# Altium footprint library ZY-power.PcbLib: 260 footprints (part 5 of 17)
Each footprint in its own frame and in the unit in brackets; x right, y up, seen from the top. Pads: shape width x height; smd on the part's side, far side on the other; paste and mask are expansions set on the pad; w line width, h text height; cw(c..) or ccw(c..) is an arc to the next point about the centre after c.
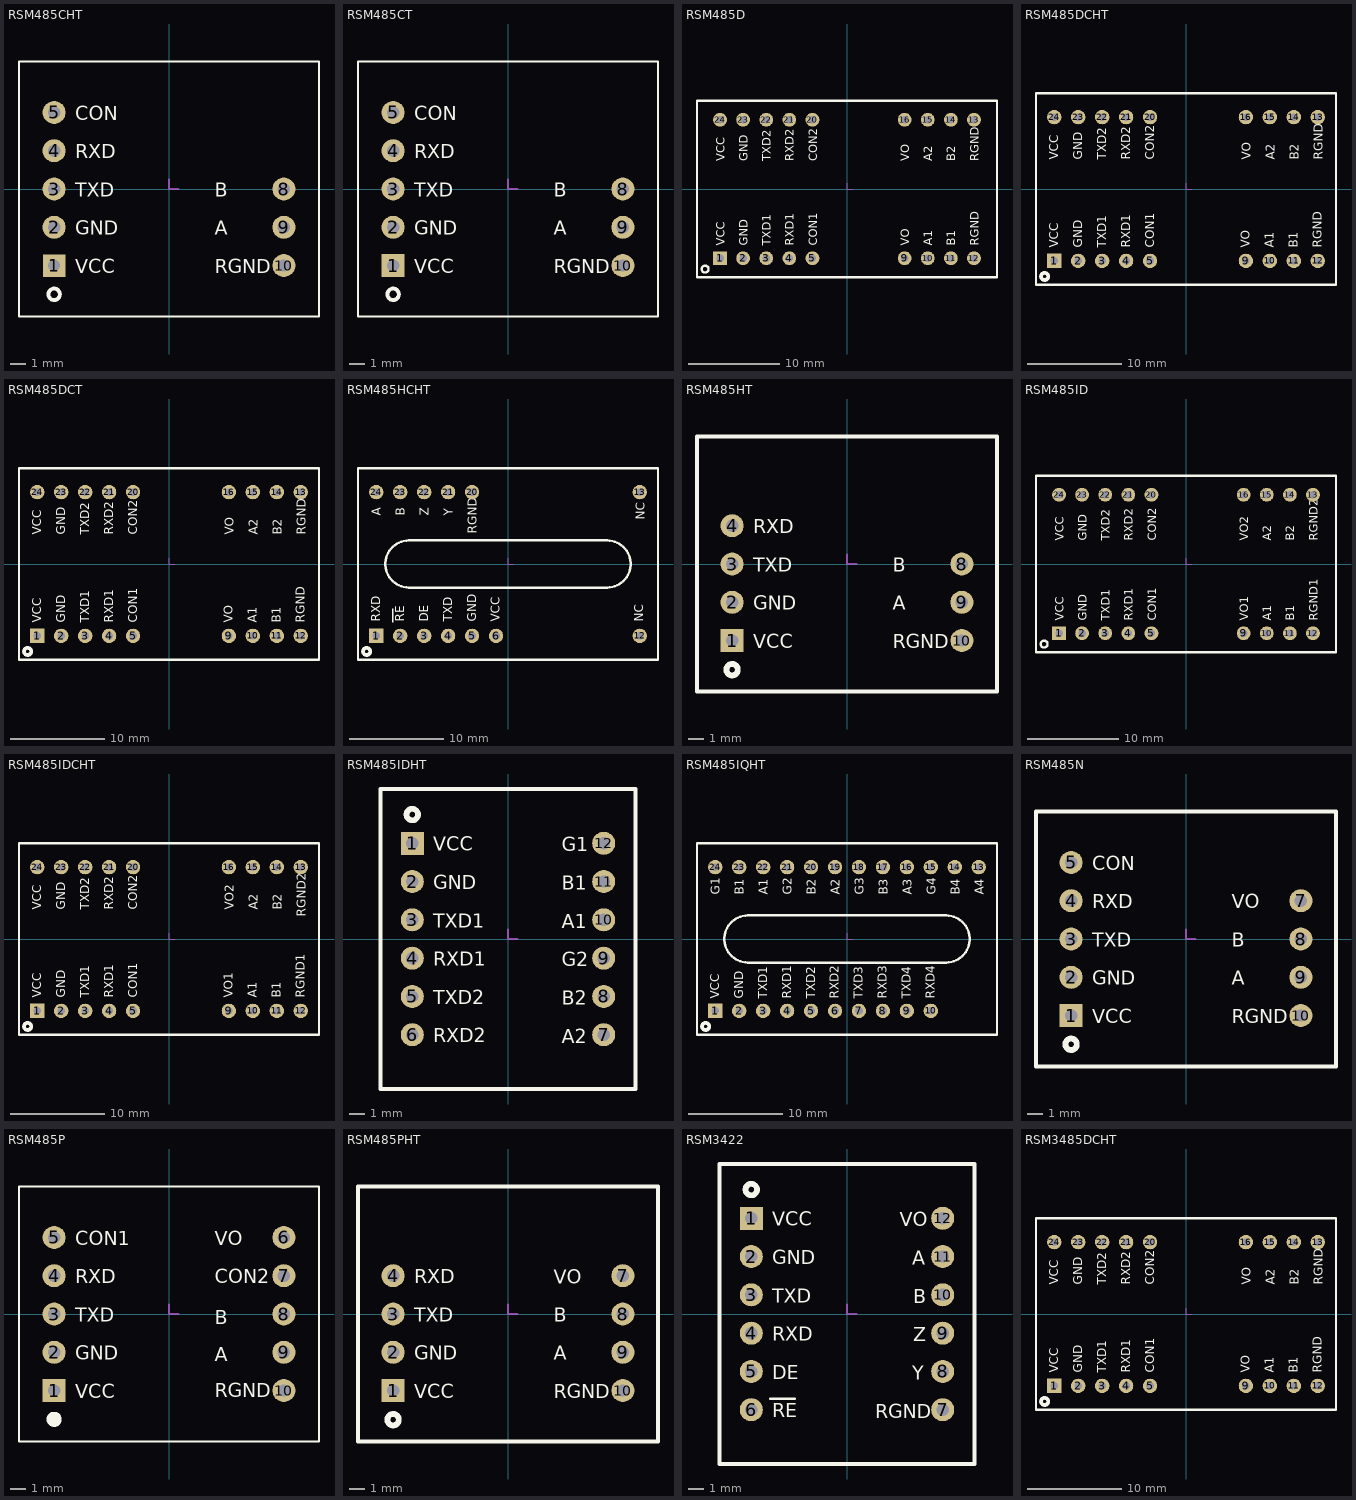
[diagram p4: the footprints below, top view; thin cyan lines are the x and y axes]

## RSM485CHT [mil] "嵌入式隔离RS-485收发器"
height 275.59
pads (8):
  rect 59.06x59.06 hole 31.5: 1(-300,-200)
  round 60 hole 32: 2(-300,-100) 3(-300,0) 4(-300,100) 5(-300,200) 8(300,0) 9(300,-100) 10(300,-200)
Top Overlay:
  circle w10: c-300,-275 r15
  lines w5: -391.73,-332.68 391.73,-332.68 391.73,332.68 -391.73,332.68 -391.73,-332.68
  text "A" at 120,-120 h36
  text "B" at 120,-20 h36
  text "RGND" at 120,-220 h36
  text "TXD" at -245,-20 h36
  text "RXD" at -245,80 h36
  text "GND" at -245,-120 h36
  text "CON" at -245,180 h36
  text "VCC" at -245,-220 h36
Mechanical 15:
  lines w5: 0,25 0,0 25,0

## RSM485CT [mil] "嵌入式隔离RS-485收发器"
height 275.59
pads (8):
  rect 60x60 hole 32: 1(-300,-200)
  round 60 hole 32: 2(-300,-100) 3(-300,0) 4(-300,100) 5(-300,200) 8(300,0) 9(300,-100) 10(300,-200)
Top Overlay:
  circle w10: c-300,-275 r15
  lines w5: -391.73,-332.68 -391.73,332.68 391.73,332.68 391.73,-332.68 -391.73,-332.68
  text "VCC" at -245,-220 h36
  text "CON" at -245,180 h36
  text "GND" at -245,-120 h36
  text "RXD" at -245,80 h36
  text "TXD" at -245,-20 h36
  text "RGND" at 120,-220 h36
  text "B" at 120,-20 h36
  text "A" at 120,-120 h36
Mechanical 15:
  lines w5: 0,25 0,0 25,0

## RSM485D [mil]
height 360
pads (18):
  rect 60x60 hole 32: 1(-550,-300)
  round 60 hole 32: 2(-450,-300) 3(-350,-300) 4(-250,-300) 5(-150,-300) 9(250,-300) 10(350,-300) 11(450,-300) 12(550,-300) 13(550,300) 14(450,300) 15(350,300) 16(250,300) 20(-150,300) 21(-250,300) 22(-350,300) 23(-450,300) 24(-550,300)
Top Overlay:
  circle w10: c-615,-347 r15
  lines w10: -650,-382 -650,382 650,382 650,-382 -650,-382
  text "VO" at 270,120 h36
  text "VO" at 270,-245 h36
  text "RGND" at 570,-245 h36
  text "A1" at 370,-245 h36
  text "B1" at 470,-245 h36
  text "RGND" at 570,120 h36
  text "A2" at 370,120 h36
  text "B2" at 470,120 h36
  text "TXD2" at -330,120 h36
  text "RXD2" at -230,120 h36
  text "GND" at -430,120 h36
  text "CON2" at -130,120 h36
  text "VCC" at -530,120 h36
  text "VCC" at -530,-245 h36
  text "CON1" at -130,-245 h36
  text "GND" at -430,-245 h36
  text "RXD1" at -230,-245 h36
  text "TXD1" at -330,-245 h36
Mechanical 15:
  lines w5: 0,25 0,0 25,0

## RSM485DCHT [mil]
height 255.91
pads (18):
  rect 60x60 hole 32: 1(-550,-300)
  round 60 hole 32: 2(-450,-300) 3(-350,-300) 4(-250,-300) 5(-150,-300) 9(250,-300) 10(350,-300) 11(450,-300) 12(550,-300) 13(550,300) 14(450,300) 15(350,300) 16(250,300) 20(-150,300) 21(-250,300) 22(-350,300) 23(-450,300) 24(-550,300)
Top Overlay:
  circle w15: c-590,-365 r15
  lines w10: -625.98,-399.61 625.98,-399.61 625.98,399.61 -625.98,399.61 -625.98,-399.61
  text "VCC" at -533,-245 h36
  text "GND" at -433,-245 h36
  text "TXD1" at -333,-245 h36
  text "RXD1" at -233,-245 h36
  text "CON1" at -133,-245 h36
  text "VO" at 267,-245 h36
  text "A1" at 367,-245 h36
  text "B1" at 467,-245 h36
  text "RGND" at 567,-245 h36
  text "RGND" at 570,123 h36
  text "B2" at 469.73,123 h36
  text "A2" at 369.45,123 h36
  text "VO" at 269.18,123 h36
  text "VCC" at -533,123 h36
  text "GND" at -432.73,123 h36
  text "TXD2" at -332.45,123 h36
  text "CON2" at -131.91,123 h36
  text "RXD2" at -232.18,123 h36
Mechanical 15:
  lines w5: 0,25 0,0 25,0

## RSM485DCT [mil]
height 374.02
pads (18):
  rect 60x60 hole 32: 1(-550,-300)
  round 60 hole 32: 2(-450,-300) 3(-350,-300) 4(-250,-300) 5(-150,-300) 9(250,-300) 10(350,-300) 11(450,-300) 12(550,-300) 13(550,300) 14(450,300) 15(350,300) 16(250,300) 20(-150,300) 21(-250,300) 22(-350,300) 23(-450,300) 24(-550,300)
Top Overlay:
  circle w15: c-590,-365 r15
  lines w10: -625.98,-399.61 -625.98,399.61 625.98,399.61 625.98,-399.61 -625.98,-399.61
  text "RXD2" at -232.18,123 h36
  text "CON2" at -131.91,123 h36
  text "TXD2" at -332.45,123 h36
  text "GND" at -432.73,123 h36
  text "VCC" at -533,123 h36
  text "VO" at 269.18,123 h36
  text "A2" at 369.45,123 h36
  text "B2" at 469.73,123 h36
  text "RGND" at 570,123 h36
  text "RGND" at 567,-245 h36
  text "B1" at 467,-245 h36
  text "A1" at 367,-245 h36
  text "VO" at 267,-245 h36
  text "CON1" at -133,-245 h36
  text "RXD1" at -233,-245 h36
  text "TXD1" at -333,-245 h36
  text "GND" at -433,-245 h36
  text "VCC" at -533,-245 h36
Mechanical 15:
  lines w5: 0,25 0,0 25,0

## RSM485HCHT [mil]
height 255.91
pads (13):
  rect 60x60 hole 32: 1(-550,-300)
  round 60 hole 32: 2(-450,-300) 3(-350,-300) 4(-250,-300) 5(-150,-300) 6(-50,-300) 12(550,-300) 13(550,300) 20(-150,300) 21(-250,300) 22(-350,300) 23(-450,300) 24(-550,300)
Top Overlay:
  circle w15: c-590,-365 r15
  lines w6: -481.1,-243 -481.1,-186.67
  lines w10: -625.98,-399.61 -625.98,399.61 625.98,399.61 625.98,-399.61 -625.98,-399.61 ; -413.39,-98.43 cw(c-413.39,0) -413.39,98.43 413.39,98.43 cw(c413.39,0) 413.39,-98.43 -413.39,-98.43
  text "VCC" at -33.56,-242 h36
  text "Y" at -231.45,201 h36
  text "RGND" at -131.27,126.94 h36
  text "Z" at -331.64,201 h36
  text "B" at -431.82,201 h36
  text "A" at -532,201 h36
  text "NC" at 570,185 h36
  text "GND" at -133.44,-242 h36
  text "TXD" at -233.33,-242 h36
  text "DE" at -333.22,-242 h36
  text "RE" at -433.11,-242 h36
  text "RXD" at -533,-242 h36
  text "NC" at 565,-242 h36
Mechanical 15:
  lines w5: 0,25 0,0 25,0

## RSM485HT [mil]
height 277.56
pads (7):
  rect 60x60 hole 32: 1(-300,-200)
  round 60 hole 32: 2(-300,-100) 3(-300,0) 4(-300,100) 8(300,0) 9(300,-100) 10(300,-200)
Top Overlay:
  circle w15: c-300,-276 r15
  lines w10: -391.73,-332.68 -391.73,332.68 391.73,332.68 391.73,-332.68 -391.73,-332.68
  text "VCC" at -245,-220 h36
  text "GND" at -245,-120 h36
  text "RXD" at -245,80 h36
  text "TXD" at -245,-20 h36
  text "RGND" at 120,-220 h36
  text "B" at 120,-20 h36
  text "A" at 120,-120 h36
Mechanical 15:
  lines w5: 0,25 0,0 25,0

## RSM485ID [mil]
height 360
pads (18):
  rect 60x60 hole 32: 1(-550,-300)
  round 60 hole 32: 2(-450,-300) 3(-350,-300) 4(-250,-300) 5(-150,-300) 9(250,-300) 10(350,-300) 11(450,-300) 12(550,-300) 13(550,300) 14(450,300) 15(350,300) 16(250,300) 20(-150,300) 21(-250,300) 22(-350,300) 23(-450,300) 24(-550,300)
Top Overlay:
  circle w10: c-615,-347 r15
  lines w10: -650,-382 -650,382 650,382 650,-382 -650,-382
  text "VO2" at 270,100 h36
  text "VO1" at 270,-245 h36
  text "RGND1" at 570,-245 h36
  text "A1" at 370,-245 h36
  text "B1" at 470,-245 h36
  text "RGND2" at 570,100 h36
  text "A2" at 370,100 h36
  text "B2" at 470,100 h36
  text "TXD2" at -330,100 h36
  text "RXD2" at -230,100 h36
  text "GND" at -430,100 h36
  text "CON2" at -130,100 h36
  text "VCC" at -530,100 h36
  text "VCC" at -530,-245 h36
  text "CON1" at -130,-245 h36
  text "GND" at -430,-245 h36
  text "RXD1" at -230,-245 h36
  text "TXD1" at -330,-245 h36
Mechanical 15:
  lines w5: 0,25 0,0 25,0

## RSM485IDCHT [mil]
height 255.91
pads (18):
  rect 60x60 hole 32: 1(-550,-300)
  round 60 hole 32: 2(-450,-300) 3(-350,-300) 4(-250,-300) 5(-150,-300) 9(250,-300) 10(350,-300) 11(450,-300) 12(550,-300) 13(550,300) 14(450,300) 15(350,300) 16(250,300) 20(-150,300) 21(-250,300) 22(-350,300) 23(-450,300) 24(-550,300)
Top Overlay:
  circle w15: c-590,-365 r15
  lines w10: -625.98,-399.61 625.98,-399.61 625.98,399.61 -625.98,399.61 -625.98,-399.61
  text "VCC" at -533,-245 h36
  text "GND" at -433,-245 h36
  text "TXD1" at -333,-245 h36
  text "RXD1" at -233,-245 h36
  text "CON1" at -133,-245 h36
  text "VO1" at 267,-245 h36
  text "A1" at 367,-245 h36
  text "B1" at 467,-245 h36
  text "RGND1" at 567,-245 h36
  text "RGND2" at 570,92 h36
  text "B2" at 469.73,123 h36
  text "A2" at 369.45,123 h36
  text "VO2" at 269.18,123 h36
  text "VCC" at -533,123 h36
  text "GND" at -432.73,123 h36
  text "TXD2" at -332.45,123 h36
  text "CON2" at -131.91,123 h36
  text "RXD2" at -232.18,123 h36
Mechanical 15:
  lines w5: 0,25 0,0 25,0

## RSM485IDHT [mil]
height 277.56
pads (12):
  rect 60x60 hole 32: 1(-250,250)
  round 60 hole 32: 2(-250,150) 3(-250,50) 4(-250,-50) 5(-250,-150) 6(-250,-250) 7(250,-250) 8(250,-150) 9(250,-50) 10(250,50) 11(250,150) 12(250,250)
Top Overlay:
  circle w15: c-250,325 r15
  lines w10: -332.68,-391.73 -332.68,391.73 332.68,391.73 332.68,-391.73 -332.68,-391.73
  text "TXD2" at -195,-170 h36
  text "RXD2" at -195,-270 h36
  text "A2" at 140.69,-272 h36
  text "B2" at 140.69,-171.8 h36
  text "RXD1" at -195,-70 h36
  text "TXD1" at -195,30 h36
  text "GND" at -195,130 h36
  text "VCC" at -195,230 h36
  text "B1" at 140.69,128.8 h36
  text "A1" at 140.69,28.6 h36
  text "G2" at 140.69,-71.6 h36
  text "G1" at 140.69,229 h36
Mechanical 15:
  lines w5: 0,25 0,0 25,0

## RSM485IQHT [mil]
height 374.02
pads (22):
  rect 60x60 hole 32: 1(-550,-300)
  round 60 hole 32: 2(-450,-300) 3(-350,-300) 4(-250,-300) 5(-150,-300) 6(-50,-300) 7(50,-300) 8(150,-300) 9(250,-300) 10(350,-300) 13(550,300) 14(450,300) 15(350,300) 16(250,300) 17(150,300) 18(50,300) 19(-50,300) 20(-150,300) 21(-250,300) 22(-350,300) 23(-450,300) 24(-550,300)
Top Overlay:
  circle w15: c-590,-365 r15
  lines w10: -625.98,-399.61 625.98,-399.61 625.98,399.61 -625.98,399.61 -625.98,-399.61 ; -413.39,-98.43 cw(c-413.39,0) -413.39,98.43 413.39,98.43 cw(c413.39,0) 413.39,-98.43 -413.39,-98.43
  text "VCC" at -533,-249 h36
  text "GND" at -433.11,-249 h36
  text "TXD1" at -333.22,-249 h36
  text "RXD1" at -233.33,-249 h36
  text "TXD2" at -133.44,-249 h36
  text "A4" at 570,185 h36
  text "B4" at 469.82,185 h36
  text "G4" at 369.64,185 h36
  text "A3" at 269.45,185 h36
  text "G1" at -532,185 h36
  text "B1" at -431.82,185 h36
  text "A1" at -331.64,185 h36
  text "B2" at -131.27,185 h36
  text "G2" at -231.45,185 h36
  text "RXD2" at -33.56,-249 h36
  text "TXD3" at 66.33,-249 h36
  text "RXD3" at 166.22,-249 h36
  text "TXD4" at 266.11,-249 h36
  text "RXD4" at 366,-249 h36
  text "B3" at 169.27,185 h36
  text "G3" at 69.09,185 h36
  text "A2" at -31.09,185 h36
Mechanical 15:
  lines w5: 0,25 0,0 25,0

## RSM485N [mil]
height 277.56
pads (9):
  rect 60x60 hole 32: 1(-300,-200)
  round 60 hole 32: 2(-300,-100) 3(-300,0) 4(-300,100) 5(-300,200) 7(300,100) 8(300,0) 9(300,-100) 10(300,-200)
Top Overlay:
  circle w15: c-300,-275 r15
  lines w10: -391.73,-332.68 391.73,-332.68 391.73,332.68 -391.73,332.68 -391.73,-332.68
  text "A" at 120,-120 h36
  text "B" at 120,-20 h36
  text "RGND" at 120,-220 h36
  text "TXD" at -245,-20 h36
  text "RXD" at -245,80 h36
  text "GND" at -245,-120 h36
  text "CON" at -245,180 h36
  text "VCC" at -245,-220 h36
  text "VO" at 120,80 h36
Mechanical 15:
  lines w5: 0,25 0,0 25,0

## RSM485P [mil]
height 277.56
pads (10):
  rect 60x60 hole 32: 1(-300,-200)
  round 60 hole 32: 2(-300,-100) 3(-300,0) 4(-300,100) 5(-300,200) 6(300,200) 7(300,100) 8(300,0) 9(300,-100) 10(300,-200)
Top Overlay:
  circle w19.68: c-300,-275 r9.84
  lines w5: -391.73,-332.68 391.73,-332.68 391.73,332.68 -391.73,332.68 -391.73,-332.68
  text "VO" at 120,180 h36
  text "CON2" at 120,80 h36
  text "VCC" at -245,-220 h36
  text "GND" at -245,-119 h36
  text "TXD" at -245,-20 h36
  text "RXD" at -245,80 h36
  text "CON1" at -245,180 h36
  text "B" at 120,-27 h36
  text "A" at 120,-123 h36
  text "RGND" at 120,-218 h36
Mechanical 15:
  lines w5: 0,25 0,0 25,0

## RSM485PHT [mil]
height 277.56
pads (8):
  rect 60x60 hole 32: 1(-300,-200)
  round 60 hole 32: 2(-300,-100) 3(-300,0) 4(-300,100) 7(300,100) 8(300,0) 9(300,-100) 10(300,-200)
Top Overlay:
  circle w15: c-300,-276 r15
  lines w10: -391.73,-332.68 -391.73,332.68 391.73,332.68 391.73,-332.68 -391.73,-332.68
  text "VCC" at -245,-220 h36
  text "GND" at -245,-120 h36
  text "RXD" at -245,80 h36
  text "TXD" at -245,-20 h36
  text "RGND" at 120,-220 h36
  text "B" at 120,-20 h36
  text "A" at 120,-120 h36
  text "VO" at 120,79 h36
Mechanical 15:
  lines w5: 0,25 0,0 25,0

## RSM3422 [mil]
height 277.56
pads (12):
  rect 60x60 hole 32: 1(-250,250)
  round 60 hole 32: 2(-250,150) 3(-250,50) 4(-250,-50) 5(-250,-150) 6(-250,-250) 7(250,-250) 8(250,-150) 9(250,-50) 10(250,50) 11(250,150) 12(250,250)
Top Overlay:
  circle w15: c-250,325 r15
  lines w6: -200.79,-221.46 -136.81,-221.46
  lines w10: -332.68,-391.73 -332.68,391.73 332.68,391.73 332.68,-391.73 -332.68,-391.73
  text "DE" at -195,-170 h36
  text "RE" at -195,-270 h36
  text "RGND" at 73.69,-272 h36
  text "Y" at 170.18,-171.8 h36
  text "RXD" at -195,-70 h36
  text "TXD" at -195,30 h36
  text "GND" at -195,130 h36
  text "VCC" at -195,230 h36
  text "A" at 170.18,128.8 h36
  text "B" at 173.61,28.6 h36
  text "Z" at 173.61,-71.6 h36
  text "VO" at 138.13,229 h36
Mechanical 15:
  lines w5: 0,25 0,0 25,0

## RSM3485DCHT [mil]
height 255.91
pads (18):
  rect 60x60 hole 32: 1(-550,-300)
  round 60 hole 32: 2(-450,-300) 3(-350,-300) 4(-250,-300) 5(-150,-300) 9(250,-300) 10(350,-300) 11(450,-300) 12(550,-300) 13(550,300) 14(450,300) 15(350,300) 16(250,300) 20(-150,300) 21(-250,300) 22(-350,300) 23(-450,300) 24(-550,300)
Top Overlay:
  circle w15: c-590,-365 r15
  lines w10: -625.98,-399.61 625.98,-399.61 625.98,399.61 -625.98,399.61 -625.98,-399.61
  text "VCC" at -533,-245 h36
  text "GND" at -433,-245 h36
  text "TXD1" at -333,-245 h36
  text "RXD1" at -233,-245 h36
  text "CON1" at -133,-245 h36
  text "VO" at 267,-245 h36
  text "A1" at 367,-245 h36
  text "B1" at 467,-245 h36
  text "RGND" at 567,-245 h36
  text "RGND" at 570,123 h36
  text "B2" at 469.73,123 h36
  text "A2" at 369.45,123 h36
  text "VO" at 269.18,123 h36
  text "VCC" at -533,123 h36
  text "GND" at -432.73,123 h36
  text "TXD2" at -332.45,123 h36
  text "CON2" at -131.91,123 h36
  text "RXD2" at -232.18,123 h36
Mechanical 15:
  lines w5: 0,25 0,0 25,0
